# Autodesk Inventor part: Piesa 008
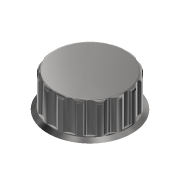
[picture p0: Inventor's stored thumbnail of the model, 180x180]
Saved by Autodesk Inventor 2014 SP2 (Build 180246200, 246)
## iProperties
Created: 2009-01
Part Number: Piesa 008
Document SubType Name: Modeling
Designer: Costel
Material: Steel
Density: 7.85 g/cm^3
Appearance: Steel - Polished
Author: Costel
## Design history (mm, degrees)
sketch "Sketch2"
  geometry: L1 (0, -2.041)-(0, 26.538) reference; L2 (0, 20)-(0, 18); L3 (-20.5, 18)-(-20.5, 0); L4 (-20.5, 0)-(-25, 0); L5 (-25, 0)-(-22.5, 1.443); L6 (-22.5, 1.443)-(-22.5, 18); L7 (-20.5, 20)-(0, 20); L8 (2.5, 0)-(-32.5, 0) reference; L9 (0, 18)-(0, 20); L10 (-4, 0)-(-6, 0); L11 (-6, 0)-(-6, 18); L12 (-4, 18)-(-4, 0); L13 (-20.5, 18)-(-6, 18); L14 (-4, 18)-(0, 18); A1 r 2 centre (-20.5, 18) between (-20.5, 20) and (-22.5, 18)
  constraints: 24 end point, 5 parallel, 4 perpendicular, 3 point on line, 2 collinear, 2 point on circle, 2 tangent, 1 centre point, 1 horizontal
  dimensions: "d0" = 50 diameter of L4.end L1; "d1" = 45 diameter of L6 L1; "d2" = 41 diameter of L3 L1; "d3" = 20 distance between parallel lines of L8 L7; "d5" = 2 radius of A1; "d6" = 8 diameter of L12 L1; "d7" = 12 diameter of L11 L1; "d8" = 2 distance between parallel lines of L13 L7; "d10" = 30 deg angle of L8 L5
revolve "Revolution1" sketch "Sketch2" stored, may be unused: angle "d11" = 90 deg
workplane "Work Plane1"
sketch "Sketch3"
  geometry: L1 (30, 0)-(-40, 0) reference; L2 (0, -30)-(0, 40) reference; C1 r 4.75 at (-26, 0)
  constraints: 1 centre point, 1 point on line
  dimensions: "d13" = 26 distance from line of L2 C1.centre; "d14" = 9.5 diameter of C1
extrude "Extrusion1" cut sketch "Sketch3" stored distance "d15" = 10; taper "d16" = 0 deg
pattern_circular "Circular Pattern1" dims angle "d18" = 360 deg
sketch "Sketch4"
  geometry: L1 (-3, -1)-(-5, -1); L2 (-5, -1)-(-5, 1); L3 (-5, 1)-(-3, 1); L4 (-3, 1)-(-3, -1); L5 (30, 0)-(-40, 0) reference; C1 r 4 at (0, 0) reference
  constraints: 8 end point, 2 parallel, 1 horizontal, 1 perpendicular, 1 other
  dimensions: "d20" = 2 distance of L1.end L2.end; "d21" = 5 distance from line of C1.centre L2; "d22" = 2 distance of L1.start L1.end
extrude "Extrusion2" cut sketch "Sketch4" distance "d23" = 18; taper "d24" = 0 deg
body "Solid1"
other parameters: "d4" = 2, "d12" = -2
